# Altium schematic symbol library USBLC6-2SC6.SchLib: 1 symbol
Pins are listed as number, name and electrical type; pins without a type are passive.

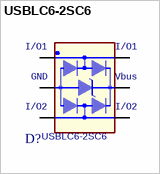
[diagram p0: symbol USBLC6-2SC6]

## USBLC6-2SC6
designator D?
footprint ST_SOT23-6L
pins: 1 I/O1, 2 GND, 3 I/O2, 4 I/O2+, 5 Vbus, 6 I/O1+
